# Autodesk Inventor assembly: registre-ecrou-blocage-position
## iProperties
Author: chr
Created: 2001-06
Part Number: registre-ecrou-blocage-position
Document SubType Name: Assemblage
Designer: chr
Control State: 0
Master: False
Checked Out: False
PropertySet Name: Design Tracking Control
Shininess: 21.0
PropertySet Name: _Private Model Information
Length Units: 11272
Angle Units: 11286
Time Units: 11279
Mass Units: 11290
Length Display Precision: 3
Angle Display Precision: 2
Compacted: False
Density: 0.0
Volumn: 0.0
Area: 0.0
PropertySet Name: Model Information
